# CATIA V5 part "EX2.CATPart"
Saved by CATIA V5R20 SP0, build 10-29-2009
Part number: EX2
Bounding box of the stored display mesh (mm): x 0 to 31.607, y -16.996 to 45, z 0 to 5
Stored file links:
  E:\Nouveau dossier\tarek\mécaniquee\Catia\TP 0\EX2.CATPart
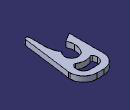
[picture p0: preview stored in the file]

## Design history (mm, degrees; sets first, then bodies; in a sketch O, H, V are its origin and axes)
Set1
  DatumSurface1 to DatumSurface21
Body1 (main body)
